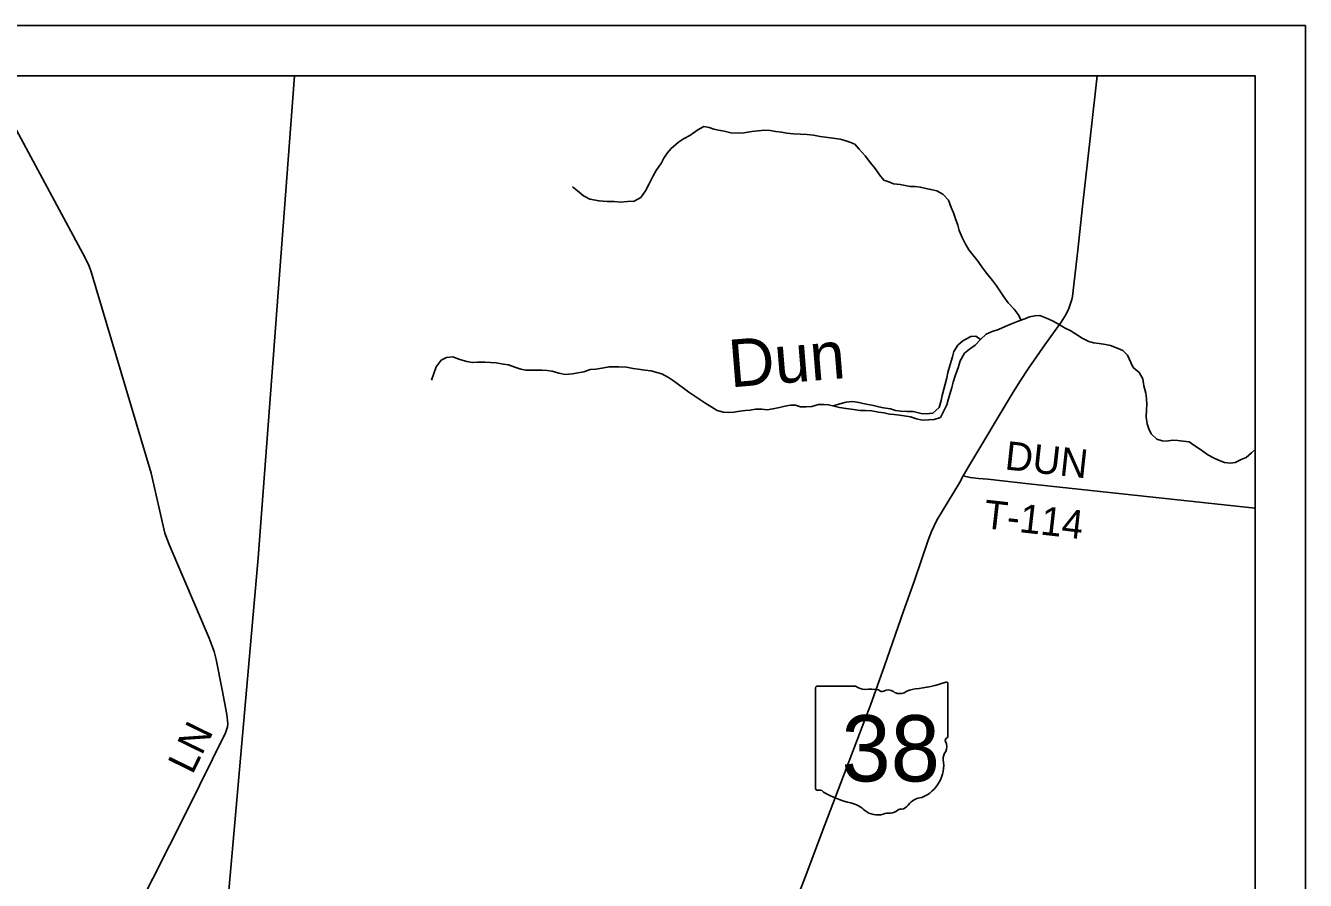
# Model space of a CAD drawing. Extents: x 0 to 36.5, y 0 to 25.3.
# Drawn here: x 6.451 to 9, y 19.299 to 21 of the extents above; entities that cross this region are included whole.
import ezdxf

# ---------------------------------------------------------------- set-up
doc = ezdxf.new("R2010")
doc.units = 0
for name, color, linetype in [('DV_X_Township_Line', 7, 'Continuous'), ('GM_X_County_Road', 7, 'Continuous'), ('GM_X_County_Road_Text', 7, 'Continuous'), ('GM_X_Minor_River', 7, 'Continuous'), ('GM_X_Minor_River_Text', 7, 'Continuous'), ('GM_X_State_Location', 7, 'Continuous'), ('GM_X_State_Route', 7, 'Continuous'), ('GM_X_State_Shield', 7, 'Continuous'), ('GM_X_Township_Road', 7, 'Continuous'), ('GM_X_Township_Road_Text', 7, 'Continuous'), ('SH_Cut_Line', 7, 'Continuous'), ('SH_Data', 7, 'Continuous')]:
    doc.layers.add(name, color=color, linetype=linetype)

msp = doc.modelspace()

# ---------------------------------------------------------------- linework, layer by layer
at = {"layer": 'DV_X_Township_Line'}
msp.add_lwpolyline([(5.1383, 16.6527), (6.6079, 15.9978), (6.7158, 17.4536), (6.7165, 17.4645), (6.7464, 17.8914), (6.7478, 17.9113), (6.7968, 18.6079), (6.9145, 19.9406), (6.9868, 20.9), (6.1845, 20.9)], dxfattribs=at)
msp.add_lwpolyline([(8.9, 14.8674), (8.9, 20.9), (6.9868, 20.9), (6.9145, 19.9406), (6.7968, 18.6079), (6.7478, 17.9113), (6.7464, 17.8914), (6.7165, 17.4645), (6.7158, 17.4536), (6.6079, 15.9978), (6.8419, 15.8878), (7.703, 15.458), (7.7552, 15.432), (7.7814, 15.4189), (7.8139, 15.4027), (8.0723, 15.2737), (8.5228, 15.0526)], close=True, dxfattribs=at)
at = {"layer": 'GM_X_County_Road'}
msp.add_lwpolyline([(6.4783, 18.8731), (6.497, 18.9052), (6.5612, 19.0216), (6.6043, 19.1042), (6.7718, 19.4348), (6.8493, 19.5924), (6.8532, 19.6042), (6.8537, 19.6103), (6.8517, 19.6288), (6.8428, 19.6775), (6.8307, 19.7382), (6.8267, 19.754), (6.8166, 19.7807), (6.7369, 19.9674), (6.7287, 19.9895), (6.7013, 20.1093), (6.5819, 20.5096), (6.5776, 20.5212), (6.5695, 20.538), (6.4286, 20.8002)], dxfattribs=at)
at = {"layer": 'GM_X_Minor_River'}
for points in [[(8.4337, 20.4138), (8.4282, 20.4251), (8.4199, 20.4354), (8.4081, 20.4483), (8.3991, 20.4601), (8.3847, 20.4818), (8.3771, 20.4928), (8.3658, 20.5066), (8.3567, 20.518), (8.348, 20.5302), (8.3298, 20.5538), (8.3223, 20.5663), (8.3162, 20.5785), (8.3106, 20.5922), (8.3075, 20.6028), (8.303, 20.6154), (8.2989, 20.6276), (8.2944, 20.6382), (8.2891, 20.6523), (8.2781, 20.6648), (8.266, 20.671), (8.2542, 20.674), (8.2443, 20.676), (8.2329, 20.6786), (8.2231, 20.6798), (8.2128, 20.6798), (8.2026, 20.6818), (8.1927, 20.6837), (8.1798, 20.6849), (8.1703, 20.6891), (8.1604, 20.6925), (8.1517, 20.7028), (8.143, 20.7158), (8.1336, 20.7268), (8.1233, 20.7409), (8.1116, 20.7542), (8.1025, 20.7638), (8.0927, 20.7683), (8.0828, 20.771), (8.0733, 20.7737), (8.0589, 20.7757), (8.0437, 20.778), (8.0334, 20.7795), (8.0205, 20.7819), (8.008, 20.7834), (7.9943, 20.7838), (7.9803, 20.7846), (7.9674, 20.7858), (7.9563, 20.7877), (7.945, 20.7889), (7.9339, 20.7909), (7.9226, 20.7917), (7.9104, 20.7905), (7.8975, 20.7891), (7.8819, 20.7868), (7.8705, 20.7861), (7.8557, 20.7865), (7.8424, 20.7896), (7.8314, 20.7919), (7.8219, 20.7939), (7.8124, 20.7969), (7.8022, 20.7989), (7.79, 20.7928), (7.774, 20.7811), (7.7615, 20.7743), (7.7516, 20.7682), (7.7367, 20.7554), (7.7291, 20.7459), (7.7222, 20.736), (7.7176, 20.7266), (7.7073, 20.7118), (7.7012, 20.7008), (7.6932, 20.6849), (7.6856, 20.6712), (7.6764, 20.6579), (7.6635, 20.6508), (7.6498, 20.65), (7.6358, 20.6486), (7.6232, 20.6497), (7.6096, 20.6502), (7.5932, 20.651), (7.575, 20.6544), (7.5621, 20.6609), (7.5504, 20.6709), (7.5401, 20.6789)], [(8.9, 20.1565), (8.8927, 20.1499), (8.8821, 20.1404), (8.8718, 20.1366), (8.86, 20.1302), (8.8505, 20.1287), (8.8391, 20.1303), (8.827, 20.1353), (8.8171, 20.1398), (8.8057, 20.1459), (8.7913, 20.1559), (8.7777, 20.165), (8.7682, 20.1715), (8.7568, 20.1731), (8.7462, 20.1742), (8.7348, 20.1746), (8.7241, 20.1731), (8.7146, 20.1732), (8.7044, 20.177), (8.693, 20.1873), (8.6881, 20.1972), (8.6847, 20.2074), (8.6829, 20.2204), (8.6837, 20.2356), (8.6841, 20.2454), (8.6837, 20.2576), (8.6819, 20.2682), (8.6785, 20.2827), (8.6762, 20.2967), (8.6687, 20.3093), (8.6573, 20.3196), (8.652, 20.3291), (8.646, 20.3439), (8.6365, 20.3535), (8.6236, 20.3588), (8.6115, 20.3634), (8.6016, 20.3653), (8.5891, 20.3673), (8.5781, 20.3688), (8.5686, 20.3715), (8.5557, 20.378), (8.5458, 20.3837), (8.5318, 20.3929), (8.5216, 20.3975), (8.5083, 20.4059), (8.4962, 20.4123), (8.4844, 20.4177), (8.4711, 20.4227), (8.4612, 20.4223), (8.4506, 20.4201), (8.4411, 20.4163), (8.4278, 20.4118), (8.4149, 20.4061), (8.4019, 20.4012), (8.3886, 20.3948), (8.3761, 20.391), (8.3639, 20.3861), (8.3532, 20.3751)], [(8.3532, 20.3751), (8.3426, 20.3638), (8.3308, 20.3562), (8.3209, 20.3479), (8.3125, 20.3327), (8.3083, 20.3187), (8.3029, 20.3046), (8.2983, 20.2902), (8.2956, 20.2796), (8.2918, 20.2663), (8.2883, 20.2549), (8.286, 20.2454), (8.2795, 20.2318), (8.273, 20.22), (8.2605, 20.2159), (8.2495, 20.2151), (8.2365, 20.2148), (8.2255, 20.2175), (8.2134, 20.2213), (8.2012, 20.2233), (8.1918, 20.2244), (8.1811, 20.2256), (8.1716, 20.2268), (8.1614, 20.2291), (8.15, 20.2306), (8.1367, 20.2329), (8.1238, 20.2337), (8.1135, 20.2338), (8.0999, 20.2357), (8.0851, 20.2377), (8.0718, 20.24), (8.0615, 20.2427), (8.0501, 20.2454), (8.0403, 20.2461), (8.0304, 20.2458), (8.0171, 20.242), (8.0057, 20.2409), (7.9943, 20.2413), (7.9848, 20.2444), (7.9742, 20.2444), (7.9632, 20.2422), (7.9529, 20.2399), (7.9396, 20.2369), (7.9282, 20.2351), (7.9176, 20.2363), (7.9046, 20.2363), (7.894, 20.2348), (7.8845, 20.2337), (7.8735, 20.2322), (7.8617, 20.2307), (7.8507, 20.23), (7.8408, 20.2304), (7.8283, 20.2339), (7.8181, 20.2407), (7.804, 20.2491), (7.7942, 20.2556), (7.7839, 20.2625), (7.7718, 20.2705), (7.7612, 20.2781), (7.7513, 20.2854), (7.7415, 20.293), (7.7316, 20.2995), (7.718, 20.3068), (7.7085, 20.3098), (7.6971, 20.3129), (7.6842, 20.3141), (7.6709, 20.316), (7.661, 20.3172), (7.6477, 20.3199), (7.6329, 20.3211), (7.623, 20.3207), (7.6132, 20.3208), (7.6025, 20.3185), (7.5866, 20.3163), (7.5756, 20.3156), (7.5626, 20.311), (7.5508, 20.3088), (7.5402, 20.3066), (7.5258, 20.3055), (7.5129, 20.3082), (7.5, 20.3124), (7.4901, 20.3135), (7.4791, 20.3143), (7.4665, 20.314), (7.457, 20.314), (7.4476, 20.3144), (7.4373, 20.316), (7.4255, 20.3198), (7.413, 20.3248), (7.4028, 20.3264), (7.388, 20.3287), (7.3769, 20.3295), (7.3656, 20.3299), (7.3511, 20.3299), (7.3409, 20.3292), (7.3299, 20.3315), (7.3158, 20.3357), (7.3022, 20.3407), (7.2892, 20.3396), (7.279, 20.3339), (7.2691, 20.3211)], [(8.3532, 20.3751), (8.3438, 20.382), (8.3335, 20.3809), (8.3179, 20.3722), (8.308, 20.3639), (8.3, 20.3514), (8.2969, 20.3407), (8.2923, 20.3252), (8.2881, 20.3096), (8.2862, 20.2986), (8.2827, 20.2865), (8.2796, 20.2762), (8.2766, 20.2637), (8.2746, 20.2538), (8.2704, 20.2398), (8.2579, 20.2288), (8.2449, 20.2273), (8.2347, 20.2281), (8.2191, 20.2316), (8.2062, 20.232), (8.1941, 20.2324), (8.1838, 20.2339), (8.1739, 20.237), (8.1599, 20.2393), (8.1504, 20.2409), (8.1398, 20.2436), (8.125, 20.2467), (8.1109, 20.2501), (8.0984, 20.2517), (8.0851, 20.2502), (8.0729, 20.2472), (8.0602, 20.243)], [(7.2691, 20.3211), (7.2641, 20.3078), (7.2595, 20.2941)]]:
    msp.add_lwpolyline(points, dxfattribs=at)
at = {"layer": 'GM_X_State_Route'}
for points in [[(8.3297, 20.1229), (8.4161, 20.2668), (8.4314, 20.2915), (8.4491, 20.3186), (8.4812, 20.3644), (8.5137, 20.4098), (8.5205, 20.4202), (8.5236, 20.4256), (8.5288, 20.4369), (8.5329, 20.4486), (8.5346, 20.4546), (8.536, 20.4606), (8.5378, 20.4729), (8.547, 20.5531), (8.5563, 20.6396), (8.5723, 20.7815), (8.5851, 20.9)], [(7.9746, 19.2293), (8.0036, 19.3047), (8.043, 19.4093), (8.1224, 19.6183), (8.1338, 19.6473), (8.162, 19.7259), (8.1996, 19.8341), (8.2207, 19.8933), (8.249, 19.9755), (8.2555, 19.993), (8.2604, 20.0044), (8.2659, 20.0155), (8.3108, 20.09), (8.3183, 20.1041), (8.3297, 20.1229)]]:
    msp.add_lwpolyline(points, dxfattribs=at)
at = {"layer": 'GM_X_State_Shield'}
for p, q in [((8.0243, 19.6815), (8.0243, 19.4814)), ((8.1041, 19.6849), (8.0269, 19.6849)), ((8.288, 19.5852), (8.288, 19.6899)), ((8.288, 19.5852), (8.288, 19.5852))]:
    msp.add_line(p, q, dxfattribs=at)
for centre, radius, start, end in [((8.0273, 19.6819), 0.00305, 98.1301, 188.1301), ((8.1225, 19.7082), 0.0296, 231.6195, 271.1119), ((8.1323, 19.5726), 0.1064, 80.4867, 94.9883), ((8.1565, 19.683), 0.00855, 219.7921, 297.1024), ((8.169, 19.6598), 0.0178, 54.4667, 119.1411), ((8.2297, 19.6238), 0.0563, 97.3462, 120.7689), ((8.1941, 19.9578), 0.2796, 275.8445, 288.9065), ((8.2851, 19.6903), 0.00294, 351.8621, 97.738), ((8.192, 19.6916), 0.0214, 233.8562, 294.8282), ((8.2873, 19.5775), 0.00454, 107.944, 210.337), ((8.2584, 19.5643), 0.0273, 340.033, 23.6496), ((8.2848, 19.5848), 0.00314, 289.6038, 7.7341), ((8.2985, 19.5414), 0.0198, 136.8065, 186.9296), ((8.2097, 19.5281), 0.0699, 292.3089, 8.9858), ((8.0274, 19.4809), 0.00308, 171.9584, 258.3066), ((8.0278, 19.5014), 0.0235, 267.339, 280.6039), ((8.0326, 19.4698), 0.00848, 29.7484, 93.2717), ((8.1397, 19.6496), 0.2019, 240.4129, 257.1985), ((8.0795, 19.3915), 0.0632, 47.1842, 75.836), ((8.1907, 19.462), 0.0226, 282.8732, 323.2771), ((8.2392, 19.4252), 0.0383, 94.4031, 142.5768), ((8.1478, 19.4688), 0.0401, 230.7004, 286.2918), ((8.171, 19.3997), 0.0329, 85.6951, 111.2099), ((8.1739, 19.4539), 0.0214, 268.777, 315.5493), ((8.1932, 19.4345), 0.00601, 65.7517, 132.6484)]:
    msp.add_arc(centre, radius, start, end, dxfattribs=at)
at = {"layer": 'GM_X_Township_Road'}
msp.add_lwpolyline([(8.3183, 20.1041), (8.3323, 20.1008), (8.3492, 20.0985), (8.3678, 20.0969), (8.4491, 20.0882), (8.9, 20.0394)], dxfattribs=at)
at = {"layer": 'SH_Cut_Line'}
msp.add_lwpolyline([(4.4591, 20.9), (3.3366, 20.9), (3.2612, 20.6041), (2.8463, 19.037), (2.6265, 18.2595), (2.5271, 17.8912), (2.5226, 17.8751), (2.5165, 17.8524), (2.5144, 17.8445), (2.4192, 17.4891), (2.3437, 17.2326), (2.3403, 17.2198), (2.1039, 16.2931), (2.1, 16.2788), (2.1, 14.1), (8.9, 14.1), (8.9, 20.9), (6.1845, 20.9)], dxfattribs=at)
at = {"layer": 'SH_Data'}
for p, q in [((6.1845, 21), (9, 21)), ((9, 21), (9, 14)), ((6.1845, 20.9), (8.9, 20.9)), ((8.9, 20.9), (8.9, 14.1))]:
    msp.add_line(p, q, dxfattribs=at)

# ---------------------------------------------------------------- texts
at = {"layer": 'GM_X_County_Road_Text'}
msp.add_text('LN', height=0.05682, rotation=63.8949, dxfattribs=at).set_placement((6.7834, 19.5077))
at = {"layer": 'GM_X_Minor_River_Text'}
msp.add_text('Dun', height=0.09469, rotation=4.6475, dxfattribs=at).set_placement((7.8548, 20.2797))
at = {"layer": 'GM_X_State_Location'}
for s in ['s', 'r']:
    msp.add_text(s, height=0.000189, dxfattribs=at).set_placement((8.5528, 20.5803))
msp.add_text('38', height=0.000189, rotation=0, dxfattribs=at).set_placement((8.5051, 20.5665))
at = {"layer": 'GM_X_State_Shield'}
msp.add_text('38', height=0.13184, dxfattribs=at).set_placement((8.076, 19.4955))
at = {"layer": 'GM_X_Township_Road_Text'}
for s, rotation, p in [('DUN', 353.73, (8.3999, 20.1167)), ('T-114', 353.535, (8.3572, 20))]:
    msp.add_text(s, height=0.05682, rotation=rotation, dxfattribs=at).set_placement(p)

doc.saveas('drawing.dxf')
